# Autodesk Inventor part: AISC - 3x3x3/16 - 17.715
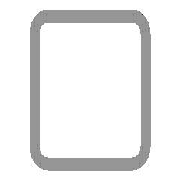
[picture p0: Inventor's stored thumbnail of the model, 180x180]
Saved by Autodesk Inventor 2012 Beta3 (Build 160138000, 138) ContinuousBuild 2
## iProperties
IsCustomPart: 1
Created: 2010-11
Part Number: AISC - 3x3x3/16 - 17.715
Material: Steel, Mild
Description: Tube
Document SubType Name: Modeling
Standard: ANSI
Designer: Beta-8540w
Standards Organization: ANSI
Language: en-US
Size Designation: 3x3x3/16
Categories: <MemberInstance><Categories><Category DisplayName="Structural Shapes" InternalName="089c4875-fa83-4c05-b084-43b9cc11f5ed" Mnemonic="GRDR"><CategoryParameter Dis
Stock Number: 3x3x3/16
Density: 7.86 g/cm^3
_CCFamilyMember: 9
_CCFamilyDisplayName: ANSI AISC (Square) - Tube
_FrameMemberDoc: Frame Member File
_Version: 15.0.0
_GetPNFromCC: 1
G_L: 17.715 in
G_W: 3.000 in
G_H: 3.000 in
Author: Beta-8540w
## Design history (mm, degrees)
node "Start plane"
node "End plane"
sketch "Sketch"
  geometry: L1 (-38.1, -28.575)-(-38.1, 28.575); L2 (-28.575, 38.1)-(28.575, 38.1); L3 (38.1, 28.575)-(38.1, -28.575); L4 (28.575, -38.1)-(-28.575, -38.1); L5 (-28.575, 33.337)-(28.575, 33.338); L6 (33.338, 28.575)-(33.338, -28.575); L7 (28.575, -33.337)-(-28.575, -33.338); L8 (-33.338, -28.575)-(-33.338, 28.575); L9 (0, 56.102)-(0, -56.102) reference; L10 (-56.102, 0)-(56.102, 0) reference; A1 r 9.525 centre (-28.575, -28.575) between (-38.1, -28.575) and (-28.575, -38.1); A2 r 9.525 centre (-28.575, 28.575) between (-28.575, 38.1) and (-38.1, 28.575); A3 r 9.525 centre (28.575, 28.575) between (38.1, 28.575) and (28.575, 38.1); A4 r 9.525 centre (28.575, -28.575) between (28.575, -38.1) and (38.1, -28.575); A5 r 4.763 centre (-28.575, 28.575) between (-28.575, 33.337) and (-33.338, 28.575); A6 r 4.763 centre (28.575, 28.575) between (33.338, 28.575) and (28.575, 33.338); A7 r 4.763 centre (28.575, -28.575) between (28.575, -33.337) and (33.338, -28.575); A8 r 4.763 centre (-28.575, -28.575) between (-33.338, -28.575) and (-28.575, -33.338)
  constraints: 16 end point, 16 point on circle, 8 centre point, 8 tangent, 4 parallel, 3 equal radius, 2 perpendicular, 7 other
  dimensions: "d10" = 76.2 distance between parallel lines of L2 L4 (= G_H); "d11" = 76.2 distance between parallel lines of L1 L3 (= G_W); "d12" = 4.7625 distance between parallel lines of L3 L6 (= G_T); "d15" = 38.1 distance between parallel lines of L2 L10 (= 0.5 x d10); "d16" = 38.1 distance between parallel lines of L9 L3 (= 0.5 x d11); "d17" = 9.525 radius of A1 (= G_IR)
extrude "Body" new body sketch "Sketch" stored distance "d3" = 449.97309 (= G_L); taper "d4" = 0 deg
node "Driven Length"
  sketch "Sketch3"
    geometry: L1 (0, 0)-(10, 0) reference
    constraints: 2 end point, 1 horizontal
  workplane "Work Plane3"
  sketch "Sketch4"
    geometry: L1 (-2, 0)-(12, 0) reference; L2 (-2, 449.973)-(12, 449.973) reference
    dimensions: "d19" = 449.97309 distance between parallel lines of L1 L2 (derived)
body "Solid1"
other parameters: "G_W" = 76.2 [user parameter; used in 1 equation term], "G_H" = 76.2 [user parameter; used in 1 equation term], "G_T" = 4.7625 [user parameter; used in 1 equation term], "G_IR" = 9.525 [user parameter; used in 1 equation term], "G_L" = 449.97309 (= d19) [user parameter; used in 1 equation term], "G_OFFSET_START" = 0 [user parameter; used in 1 equation term], "G_OFFSET_END" = 0 [user parameter; used in 1 equation term], "d13" = 0 (computed from G_OFFSET_START), "d14" = 449.97309 (= G_OFFSET_END + B_L), "B_L" = 449.97309 [user parameter; used in 1 equation term], "d18" = 90 deg
